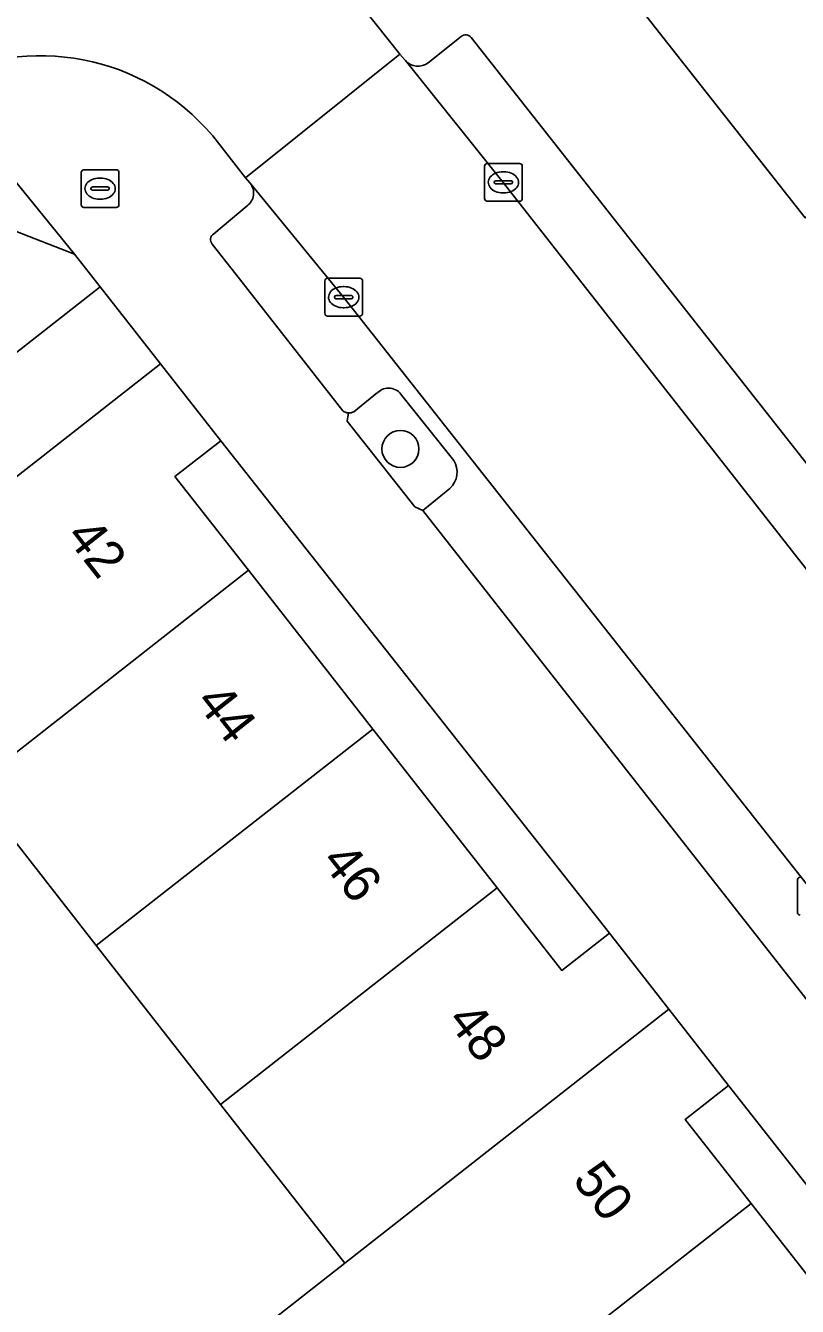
# Model space of a CAD drawing. Extents: x 160377 to 161131, y 383938 to 384853.
# Drawn here: x 160744.25 to 160764.68, y 384357.77 to 384391.67 of the extents above; entities that cross this region are included whole.
import ezdxf

# ---------------------------------------------------------------- set-up
doc = ezdxf.new("R2010")
doc.units = 0
for name, color, linetype in [('IMGEO_Boom', 7, 'Continuous'), ('IMGEO_Brandkraan', 7, 'Continuous'), ('IMGEO_Erf', 7, 'Continuous'), ('IMGEO_Groenvoorziening', 7, 'Continuous'), ('IMGEO_Kolk', 7, 'Continuous'), ('IMGEO_Pand', 7, 'Continuous'), ('IMGEO_Pand_nummerreeks', 7, 'Continuous'), ('IMGEO_Parkeervlak_open', 7, 'Continuous'), ('IMGEO_Rijbaan_lokaal_open', 7, 'Continuous'), ('IMGEO_Voetpad_open', 7, 'Continuous')]:
    doc.layers.add(name, color=color, linetype=linetype)

msp = doc.modelspace()

# ---------------------------------------------------------------- linework, layer by layer
at = {"layer": 'IMGEO_Boom'}
msp.add_circle((160754.168, 384380.463), 0.489, dxfattribs=at)
at = {"layer": 'IMGEO_Brandkraan'}
for p, q in [((160745.792, 384387.853), (160746.644, 384387.853)), ((160745.717, 384386.927), (160745.717, 384387.779)), ((160746.205, 384387.633), (160746.23, 384387.633)), ((160746.718, 384387.779), (160746.718, 384386.927)), ((160745.976, 384387.347), (160745.976, 384387.359)), ((160746.414, 384387.31), (160746.016, 384387.31)), ((160746.019, 384387.396), (160746.417, 384387.396)), ((160746.46, 384387.359), (160746.46, 384387.347)), ((160746.644, 384386.853), (160745.792, 384386.853)), ((160746.228, 384387.073), (160746.203, 384387.073))]:
    msp.add_line(p, q, dxfattribs=at)
for points in [[(160745.792, 384387.853), (160746.644, 384387.853)], [(160745.717, 384386.927), (160745.717, 384387.779)], [(160746.718, 384387.779), (160746.718, 384386.927)], [(160746.644, 384386.853), (160745.792, 384386.853)]]:
    msp.add_lwpolyline(points, dxfattribs=at)
for centre, radius, start, end in [((160745.794, 384387.777), 0.0765, 91.552, 178.448), ((160745.794, 384387.777), 0.0765, 91.552, 178.448), ((160746.642, 384387.777), 0.0765, 1.552, 88.448), ((160746.642, 384387.777), 0.0765, 1.552, 88.448), ((160746.016, 384387.356), 0.0403, 85.8775, 175.7526), ((160746.013, 384387.346), 0.0366, 178.938, 274.7102), ((160746.417, 384387.353), 0.043, 264.8664, 352.4533), ((160746.421, 384387.358), 0.0386, 1.7309, 96.639), ((160745.794, 384386.929), 0.0765, 181.552, 268.448), ((160745.794, 384386.929), 0.0765, 181.552, 268.448), ((160746.642, 384386.929), 0.0765, 271.552, 358.448), ((160746.642, 384386.929), 0.0765, 271.552, 358.448)]:
    msp.add_arc(centre, radius, start, end, dxfattribs=at)
for centre, major_axis, ratio, start_param, end_param in [((160746.204, 384387.353), (-0.387, 0.002), 0.722429, 4.712389, 7.853982), ((160746.229, 384387.353), (-0.39, 0.002), 0.717154, 1.570796, 4.712389)]:
    msp.add_ellipse(centre, major_axis=major_axis, ratio=ratio, start_param=start_param, end_param=end_param, dxfattribs=at)
at = {"layer": 'IMGEO_Erf'}
for points in [[(160743.844, 384382.891), (160746.222, 384384.753), (160745.545, 384385.618), (160741.205, 384387.3)], [(160770.365, 384331.67), (160772.644, 384333.455), (160772.548, 384333.577), (160769.319, 384337.699), (160765.995, 384341.943), (160762.672, 384346.186), (160759.348, 384350.429), (160756.024, 384354.672), (160753.031, 384352.329), (160749.708, 384356.573), (160752.701, 384358.916), (160749.409, 384363.118), (160746.119, 384367.319), (160742.828, 384371.52)]]:
    msp.add_lwpolyline(points, dxfattribs=at)
for points in [[(160749.411, 384380.682), (160748.2, 384379.733), (160750.144, 384377.251), (160753.435, 384373.05), (160756.726, 384368.849), (160758.439, 384366.662), (160759.699, 384367.649)], [(160762.855, 384363.62), (160761.707, 384362.721), (160763.454, 384360.491), (160766.777, 384356.248), (160770.101, 384352.005), (160773.425, 384347.762), (160776.748, 384343.519), (160778.465, 384341.327), (160779.656, 384342.26)]]:
    msp.add_lwpolyline(points, close=True, dxfattribs=at)
at = {"layer": 'IMGEO_Groenvoorziening'}
for points in [[(160753.566, 384381.956), (160752.935, 384381.447)], [(160755.578, 384380.16), (160754.208, 384381.879)], [(160752.792, 384381.417), (160752.762, 384381.196), (160754.554, 384378.929), (160754.76, 384378.834), (160755.478, 384379.419)]]:
    msp.add_lwpolyline(points, dxfattribs=at)
for centre, radius, start, end in [((160753.856, 384381.655), 0.417, 32.3946, 133.9269), ((160752.81, 384381.686), 0.269, 266.1127, 297.5838), ((160755.089, 384379.849), 0.58, 312.1519, 32.4765)]:
    msp.add_arc(centre, radius, start, end, dxfattribs=at)
at = {"layer": 'IMGEO_Kolk'}
for p, q in [((160756.394, 384387.093), (160756.394, 384387.945)), ((160756.469, 384388.019), (160757.321, 384388.019)), ((160756.882, 384387.799), (160756.907, 384387.799)), ((160757.395, 384387.945), (160757.395, 384387.093)), ((160756.653, 384387.513), (160756.653, 384387.525)), ((160757.091, 384387.476), (160756.693, 384387.476)), ((160756.696, 384387.562), (160757.094, 384387.562)), ((160757.137, 384387.525), (160757.137, 384387.513)), ((160756.905, 384387.239), (160756.88, 384387.239)), ((160757.321, 384387.019), (160756.469, 384387.019)), ((160752.166, 384384.054), (160752.166, 384384.906)), ((160752.241, 384384.98), (160753.093, 384384.98)), ((160752.654, 384384.76), (160752.679, 384384.76)), ((160753.167, 384384.906), (160753.167, 384384.054)), ((160752.425, 384384.474), (160752.425, 384384.486)), ((160752.863, 384384.437), (160752.465, 384384.437)), ((160752.468, 384384.523), (160752.866, 384384.523)), ((160752.909, 384384.486), (160752.909, 384384.474)), ((160752.677, 384384.2), (160752.652, 384384.2)), ((160753.093, 384383.98), (160752.241, 384383.98)), ((160764.676, 384368.201), (160764.676, 384369.053))]:
    msp.add_line(p, q, dxfattribs=at)
for points in [[(160756.394, 384387.093), (160756.394, 384387.945)], [(160756.469, 384388.019), (160757.321, 384388.019)], [(160757.395, 384387.945), (160757.395, 384387.093)], [(160757.321, 384387.019), (160756.469, 384387.019)], [(160752.166, 384384.054), (160752.166, 384384.906)], [(160752.241, 384384.98), (160753.093, 384384.98)], [(160753.167, 384384.906), (160753.167, 384384.054)], [(160753.093, 384383.98), (160752.241, 384383.98)], [(160764.676, 384368.201), (160764.676, 384369.053)]]:
    msp.add_lwpolyline(points, dxfattribs=at)
for centre, radius, start, end in [((160756.471, 384387.943), 0.0765, 91.552, 178.448), ((160756.471, 384387.943), 0.0765, 91.552, 178.448), ((160757.319, 384387.943), 0.0765, 1.552, 88.448), ((160757.319, 384387.943), 0.0765, 1.552, 88.448), ((160756.693, 384387.522), 0.0403, 85.8775, 175.7526), ((160756.69, 384387.512), 0.0366, 178.938, 274.7102), ((160757.094, 384387.519), 0.043, 264.8664, 352.4533), ((160757.098, 384387.524), 0.0386, 1.7309, 96.639), ((160756.471, 384387.095), 0.0765, 181.552, 268.448), ((160756.471, 384387.095), 0.0765, 181.552, 268.448), ((160757.319, 384387.095), 0.0765, 271.552, 358.448), ((160757.319, 384387.095), 0.0765, 271.552, 358.448), ((160752.243, 384384.904), 0.0765, 91.552, 178.448), ((160752.243, 384384.904), 0.0765, 91.552, 178.448), ((160753.091, 384384.904), 0.0765, 1.552, 88.448), ((160753.091, 384384.904), 0.0765, 1.552, 88.448), ((160752.465, 384384.483), 0.0403, 85.8775, 175.7526), ((160752.462, 384384.473), 0.0366, 178.938, 274.7102), ((160752.866, 384384.48), 0.043, 264.8664, 352.4533), ((160752.87, 384384.485), 0.0386, 1.7309, 96.639), ((160752.243, 384384.056), 0.0765, 181.552, 268.448), ((160752.243, 384384.056), 0.0765, 181.552, 268.448), ((160753.091, 384384.056), 0.0765, 271.552, 358.448), ((160753.091, 384384.056), 0.0765, 271.552, 358.448), ((160764.753, 384369.051), 0.0765, 91.552, 178.448), ((160764.753, 384369.051), 0.0765, 91.552, 178.448), ((160764.753, 384368.203), 0.0765, 181.552, 268.448), ((160764.753, 384368.203), 0.0765, 181.552, 268.448)]:
    msp.add_arc(centre, radius, start, end, dxfattribs=at)
for centre, major_axis, ratio, start_param, end_param in [((160756.881, 384387.519), (-0.387, 0.002), 0.722429, 4.712389, 7.853982), ((160756.906, 384387.519), (-0.39, 0.002), 0.717154, 1.570796, 4.712389), ((160752.653, 384384.48), (-0.387, 0.002), 0.722429, 4.712389, 7.853982), ((160752.678, 384384.48), (-0.39, 0.002), 0.717154, 1.570796, 4.712389)]:
    msp.add_ellipse(centre, major_axis=major_axis, ratio=ratio, start_param=start_param, end_param=end_param, dxfattribs=at)
at = {"layer": 'IMGEO_Pand'}
for points in [[(160775.448, 384390.597), (160773.378, 384393.227), (160779.374, 384397.95), (160773.357, 384405.825), (160767.259, 384401.021), (160766.058, 384400.075), (160764.987, 384401.544), (160760.252, 384397.828), (160761.346, 384396.399), (160760.2, 384395.495), (160758.762, 384394.36), (160764.882, 384386.58), (160766.279, 384387.696), (160768.391, 384385.012)], [(160747.817, 384382.717), (160746.222, 384384.753), (160743.844, 384382.891), (160741.29, 384386.151), (160732.713, 384379.433), (160736.862, 384374.136)], [(160747.817, 384382.717), (160736.862, 384374.136), (160737.046, 384373.901), (160740.4, 384369.619), (160742.828, 384371.52), (160750.144, 384377.251), (160748.2, 384379.733), (160749.411, 384380.682)], [(160746.119, 384367.319), (160753.435, 384373.05), (160750.144, 384377.251), (160742.828, 384371.52)], [(160746.119, 384367.319), (160749.409, 384363.118), (160756.726, 384368.849), (160753.435, 384373.05)], [(160749.409, 384363.118), (160752.701, 384358.916), (160761.277, 384365.634), (160759.699, 384367.649), (160758.439, 384366.662), (160756.726, 384368.849)], [(160763.454, 384360.491), (160761.707, 384362.721), (160762.855, 384363.62), (160761.277, 384365.634), (160752.701, 384358.916), (160749.708, 384356.573), (160753.031, 384352.329), (160756.024, 384354.672)], [(160756.024, 384354.672), (160759.348, 384350.429), (160766.777, 384356.248), (160763.454, 384360.491)]]:
    msp.add_lwpolyline(points, close=True, dxfattribs=at)
at = {"layer": 'IMGEO_Parkeervlak_open'}
for points in [[(160755.773, 384391.376), (160754.906, 384390.685)], [(160766.444, 384378.123), (160765.382, 384379.49), (160756.043, 384391.348)], [(160754.3, 384390.745), (160756.891, 384387.518), (160769.169, 384371.854), (160771.935, 384368.374), (160772.415, 384367.771), (160773.293, 384366.66), (160773.707, 384366.301), (160789.695, 384345.758)], [(160773.069, 384358.615), (160769.555, 384362.982), (160769.109, 384363.537), (160768.486, 384364.333), (160767.853, 384365.154), (160765.174, 384368.627), (160752.664, 384384.48), (160750.192, 384387.495)], [(160750.108, 384386.895), (160749.228, 384386.154)], [(160749.187, 384385.882), (160749.811, 384385.092), (160752.644, 384381.47)], [(160752.935, 384381.447), (160753.566, 384381.956)], [(160754.208, 384381.879), (160755.578, 384380.16)], [(160755.478, 384379.419), (160754.76, 384378.834), (160765.382, 384365.301)]]:
    msp.add_lwpolyline(points, dxfattribs=at)
for centre, radius, start, end in [((160755.894, 384391.231), 0.189, 38.1358, 130.023), ((160754.634, 384391.027), 0.437, 220.1687, 308.5225), ((160749.861, 384387.235), 0.421, 305.9471, 38.1137), ((160749.32, 384386.001), 0.179, 121.0896, 221.7664), ((160753.856, 384381.655), 0.417, 32.3946, 133.9269), ((160752.809, 384381.697), 0.281, 234.0297, 266.5646), ((160752.81, 384381.686), 0.269, 266.1127, 297.5838), ((160755.089, 384379.849), 0.58, 312.1519, 32.4765)]:
    msp.add_arc(centre, radius, start, end, dxfattribs=at)
at = {"layer": 'IMGEO_Rijbaan_lokaal_open'}
for points in [[(160749.199, 384388.748), (160750.065, 384387.637), (160754.157, 384390.91), (160752.542, 384392.949), (160751.945, 384393.605), (160751.239, 384394.454)], [(160789.695, 384345.758), (160773.707, 384366.301), (160773.293, 384366.66), (160772.415, 384367.771), (160771.935, 384368.374), (160769.169, 384371.854), (160756.891, 384387.518), (160754.3, 384390.745), (160754.286, 384390.762), (160754.157, 384390.91), (160750.065, 384387.637), (160750.18, 384387.51), (160750.192, 384387.495), (160752.664, 384384.48), (160765.174, 384368.627), (160767.853, 384365.154), (160768.486, 384364.333), (160769.109, 384363.537), (160769.555, 384362.982), (160773.069, 384358.615), (160783.415, 384345.455)]]:
    msp.add_lwpolyline(points, dxfattribs=at)
msp.add_arc((160744.643, 384384.916), 5.953, 40.0682, 118.1094, dxfattribs=at)
at = {"layer": 'IMGEO_Voetpad_open'}
for points in [[(160764.882, 384386.58), (160758.762, 384394.36), (160748.362, 384406.96), (160741.944, 384414.5), (160721.567, 384438.53), (160721.366, 384438.767), (160720.563, 384439.711), (160689.656, 384476.059), (160679.533, 384487.97), (160676.022, 384486.022), (160676.495, 384485.485), (160676.55, 384485.42)], [(160742.128, 384406.092), (160742.137, 384406.08), (160744.866, 384402.636), (160747.654, 384404.799), (160755.317, 384395.174), (160752.542, 384392.949), (160754.157, 384390.91), (160754.286, 384390.762), (160754.3, 384390.745)], [(160754.906, 384390.685), (160755.773, 384391.376)], [(160756.043, 384391.348), (160765.382, 384379.49), (160766.444, 384378.123)], [(160741.205, 384387.3), (160745.545, 384385.618), (160741.838, 384390.167)], [(160741.838, 384390.167), (160745.545, 384385.618), (160746.222, 384384.753), (160747.817, 384382.717), (160749.411, 384380.682), (160759.699, 384367.649), (160761.277, 384365.634), (160762.855, 384363.62), (160779.656, 384342.26), (160781.263, 384340.208), (160782.871, 384338.156), (160783.548, 384337.293), (160784.24, 384332.486), (160784.161, 384332.424), (160785.23, 384331.026)], [(160750.192, 384387.495), (160750.18, 384387.51), (160750.065, 384387.637), (160749.199, 384388.748)], [(160749.228, 384386.154), (160750.108, 384386.895)], [(160752.644, 384381.47), (160749.811, 384385.092), (160749.187, 384385.882)], [(160765.382, 384365.301), (160754.76, 384378.834), (160754.554, 384378.929), (160752.762, 384381.196), (160752.792, 384381.417)]]:
    msp.add_lwpolyline(points, dxfattribs=at)
for centre, radius, start, end in [((160755.894, 384391.231), 0.189, 38.1358, 130.023), ((160744.643, 384384.916), 5.953, 40.0682, 118.1094), ((160754.634, 384391.027), 0.437, 220.1687, 308.5225), ((160749.861, 384387.235), 0.421, 305.9471, 38.1137), ((160749.32, 384386.001), 0.179, 121.0896, 221.7664), ((160752.809, 384381.697), 0.281, 234.0297, 266.5646)]:
    msp.add_arc(centre, radius, start, end, dxfattribs=at)

# ---------------------------------------------------------------- texts
at = {"layer": 'IMGEO_Pand_nummerreeks'}
for s, rotation, p in [('42', 308.071, (160745.282, 384378.14)), ('44', 308.2624, (160748.72, 384373.76)), ('46', 308.2624, (160752.045, 384369.543)), ('48', 308.2624, (160755.373, 384365.325)), ('50', 308.2619, (160758.697, 384361.109))]:
    msp.add_text(s, height=1, rotation=rotation, dxfattribs=at).set_placement(p)

doc.saveas('drawing.dxf')
